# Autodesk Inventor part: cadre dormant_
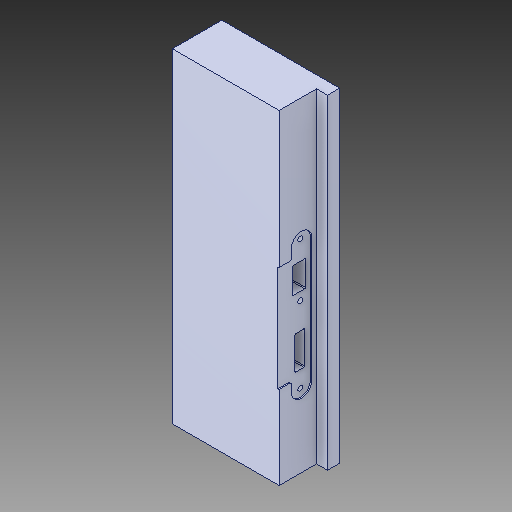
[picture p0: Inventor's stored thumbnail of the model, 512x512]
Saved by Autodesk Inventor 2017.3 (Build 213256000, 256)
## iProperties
Created: 2011-02
Part Number: cadre dormant_
Material: Générique
Document SubType Name: Modeling
Designer: ficho
Density: 1 g/cm^3
Appearance: Par défaut
Author: ficho
Sending System: SolidWorks 2009
Last Author: christophe
Last Saved: 2011-02-10
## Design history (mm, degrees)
feature "Enlèv. mat.-Extru.1"
node "Solide1"
